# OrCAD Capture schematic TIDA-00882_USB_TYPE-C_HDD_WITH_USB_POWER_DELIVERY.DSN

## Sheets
1 01_BLOCK_DIAGRAM: title: TIDA-00882: USB Type-C HDD; rev: A.0; company: Texas Instruments, CIS/ICP
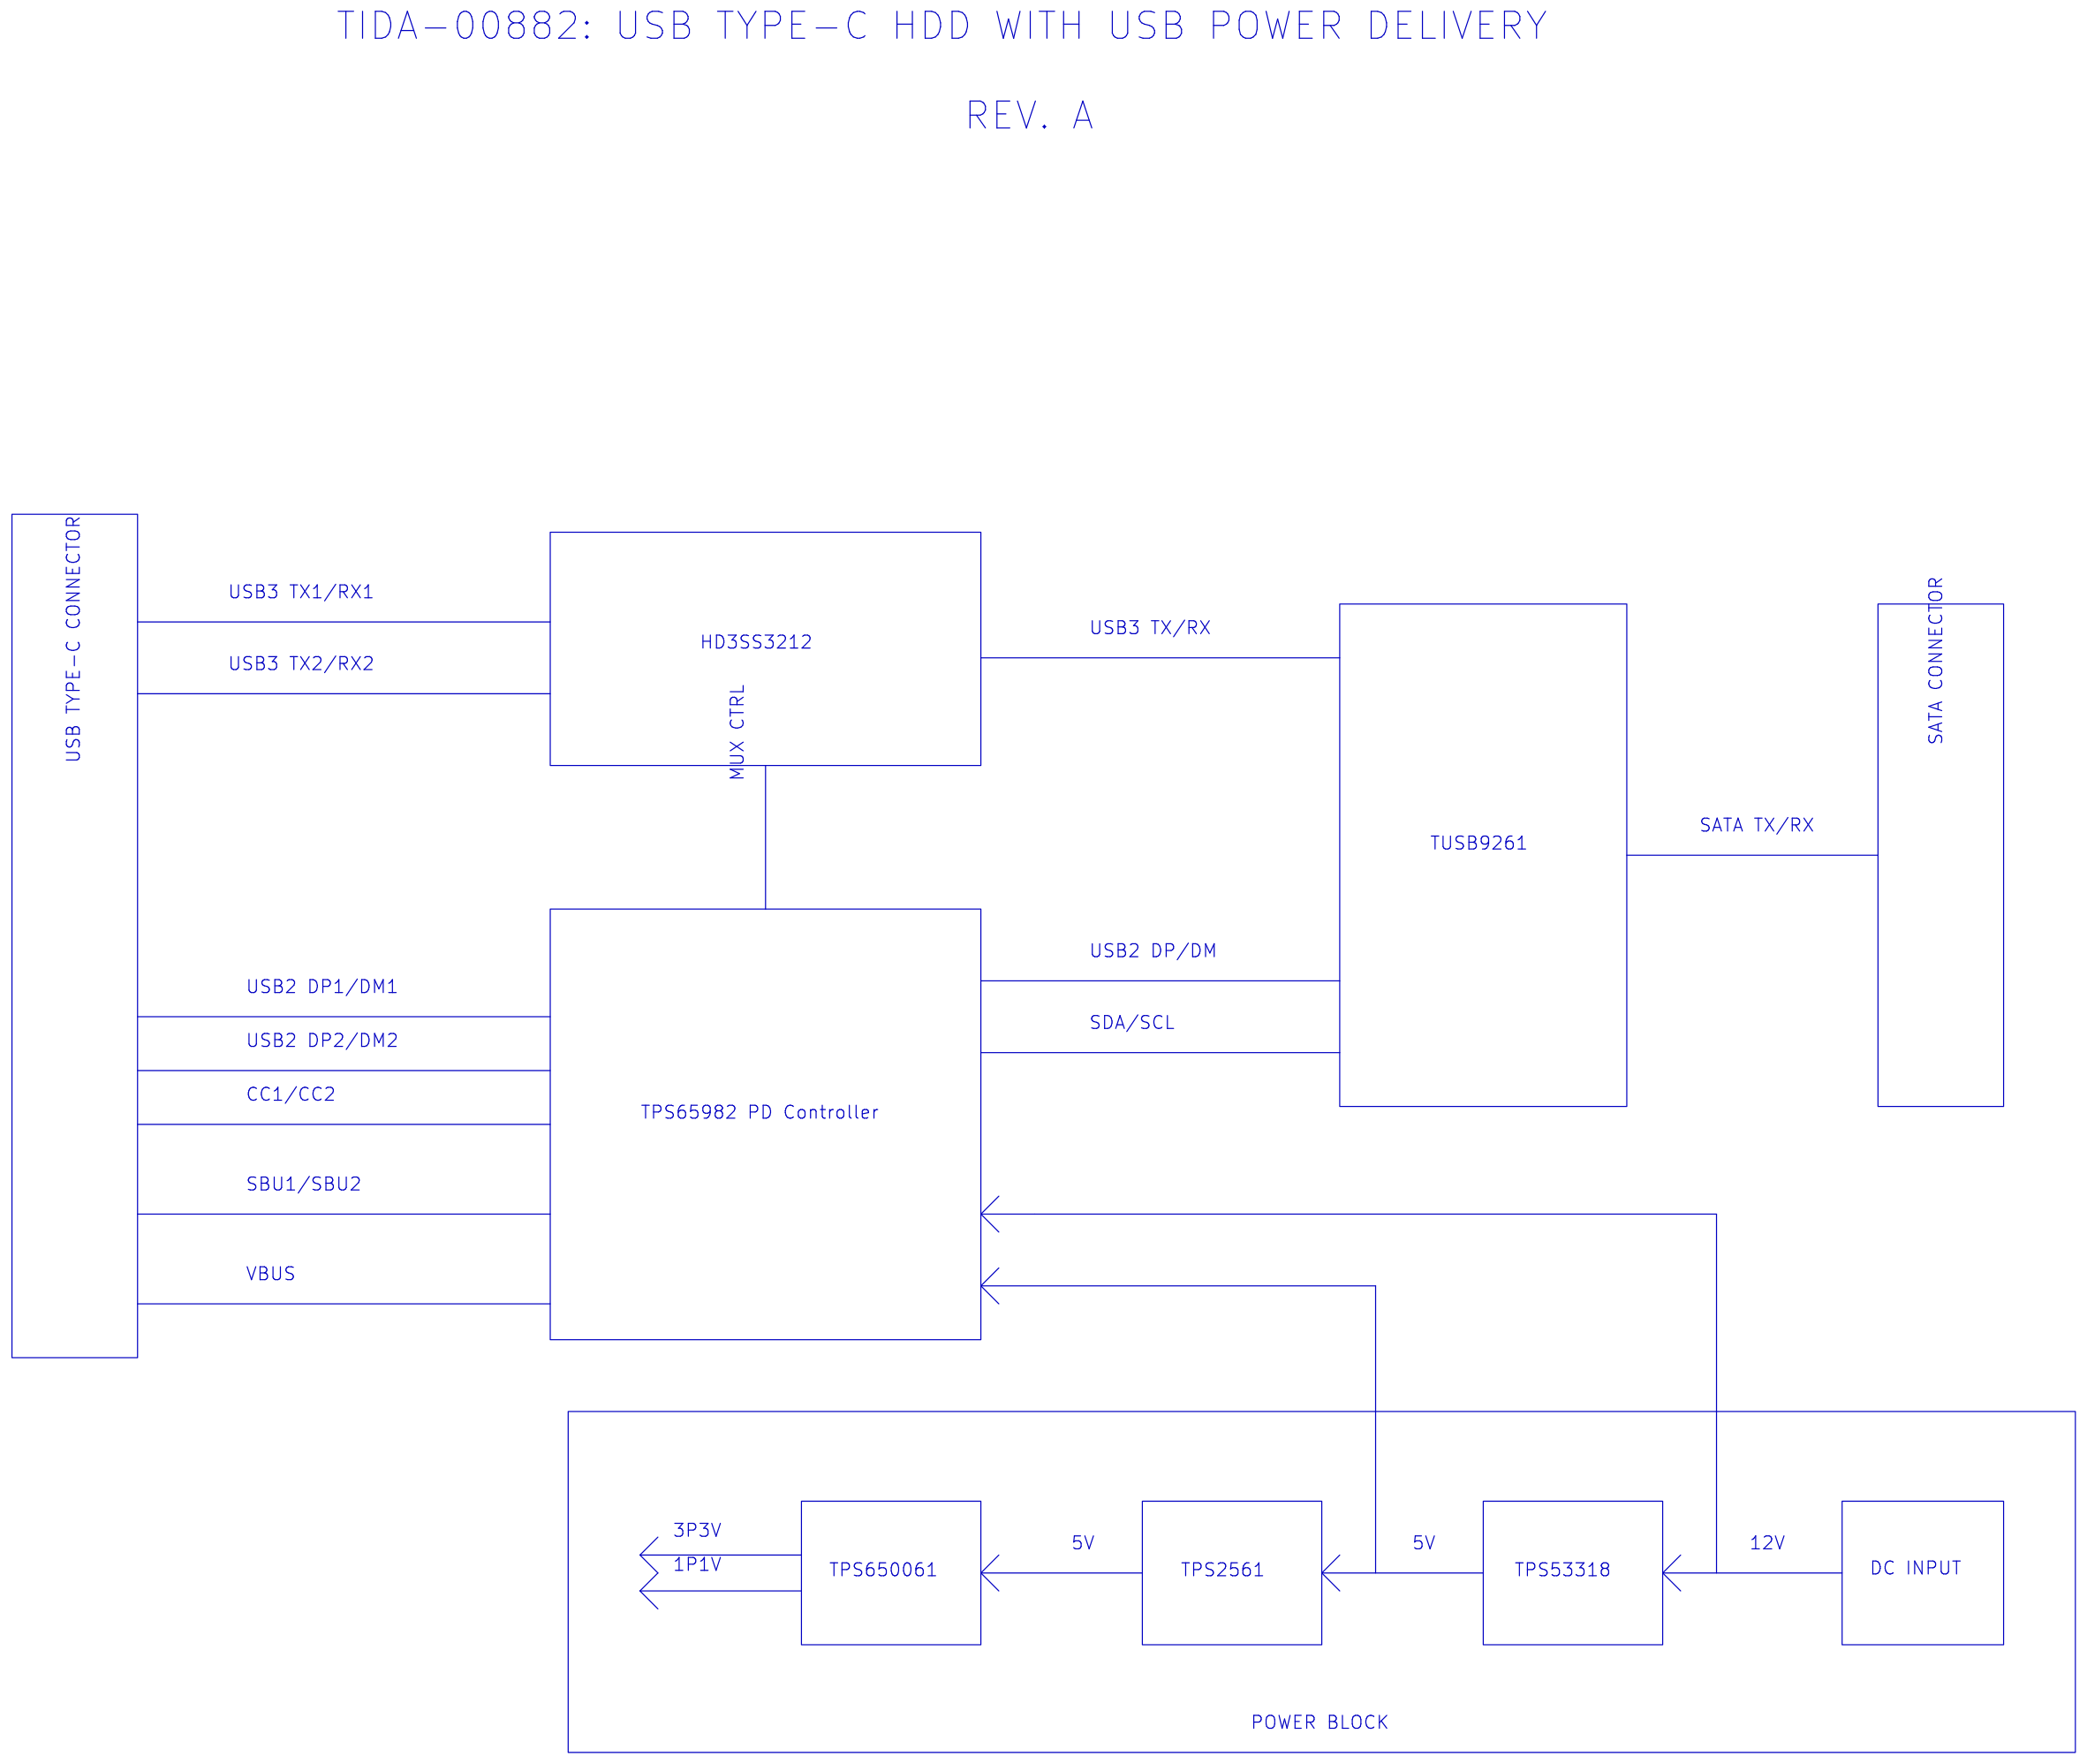
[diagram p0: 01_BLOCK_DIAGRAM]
2 02_HD3SS3212: size C; title: TIDA-00882: USB Type-C HDD: HD3SS3212
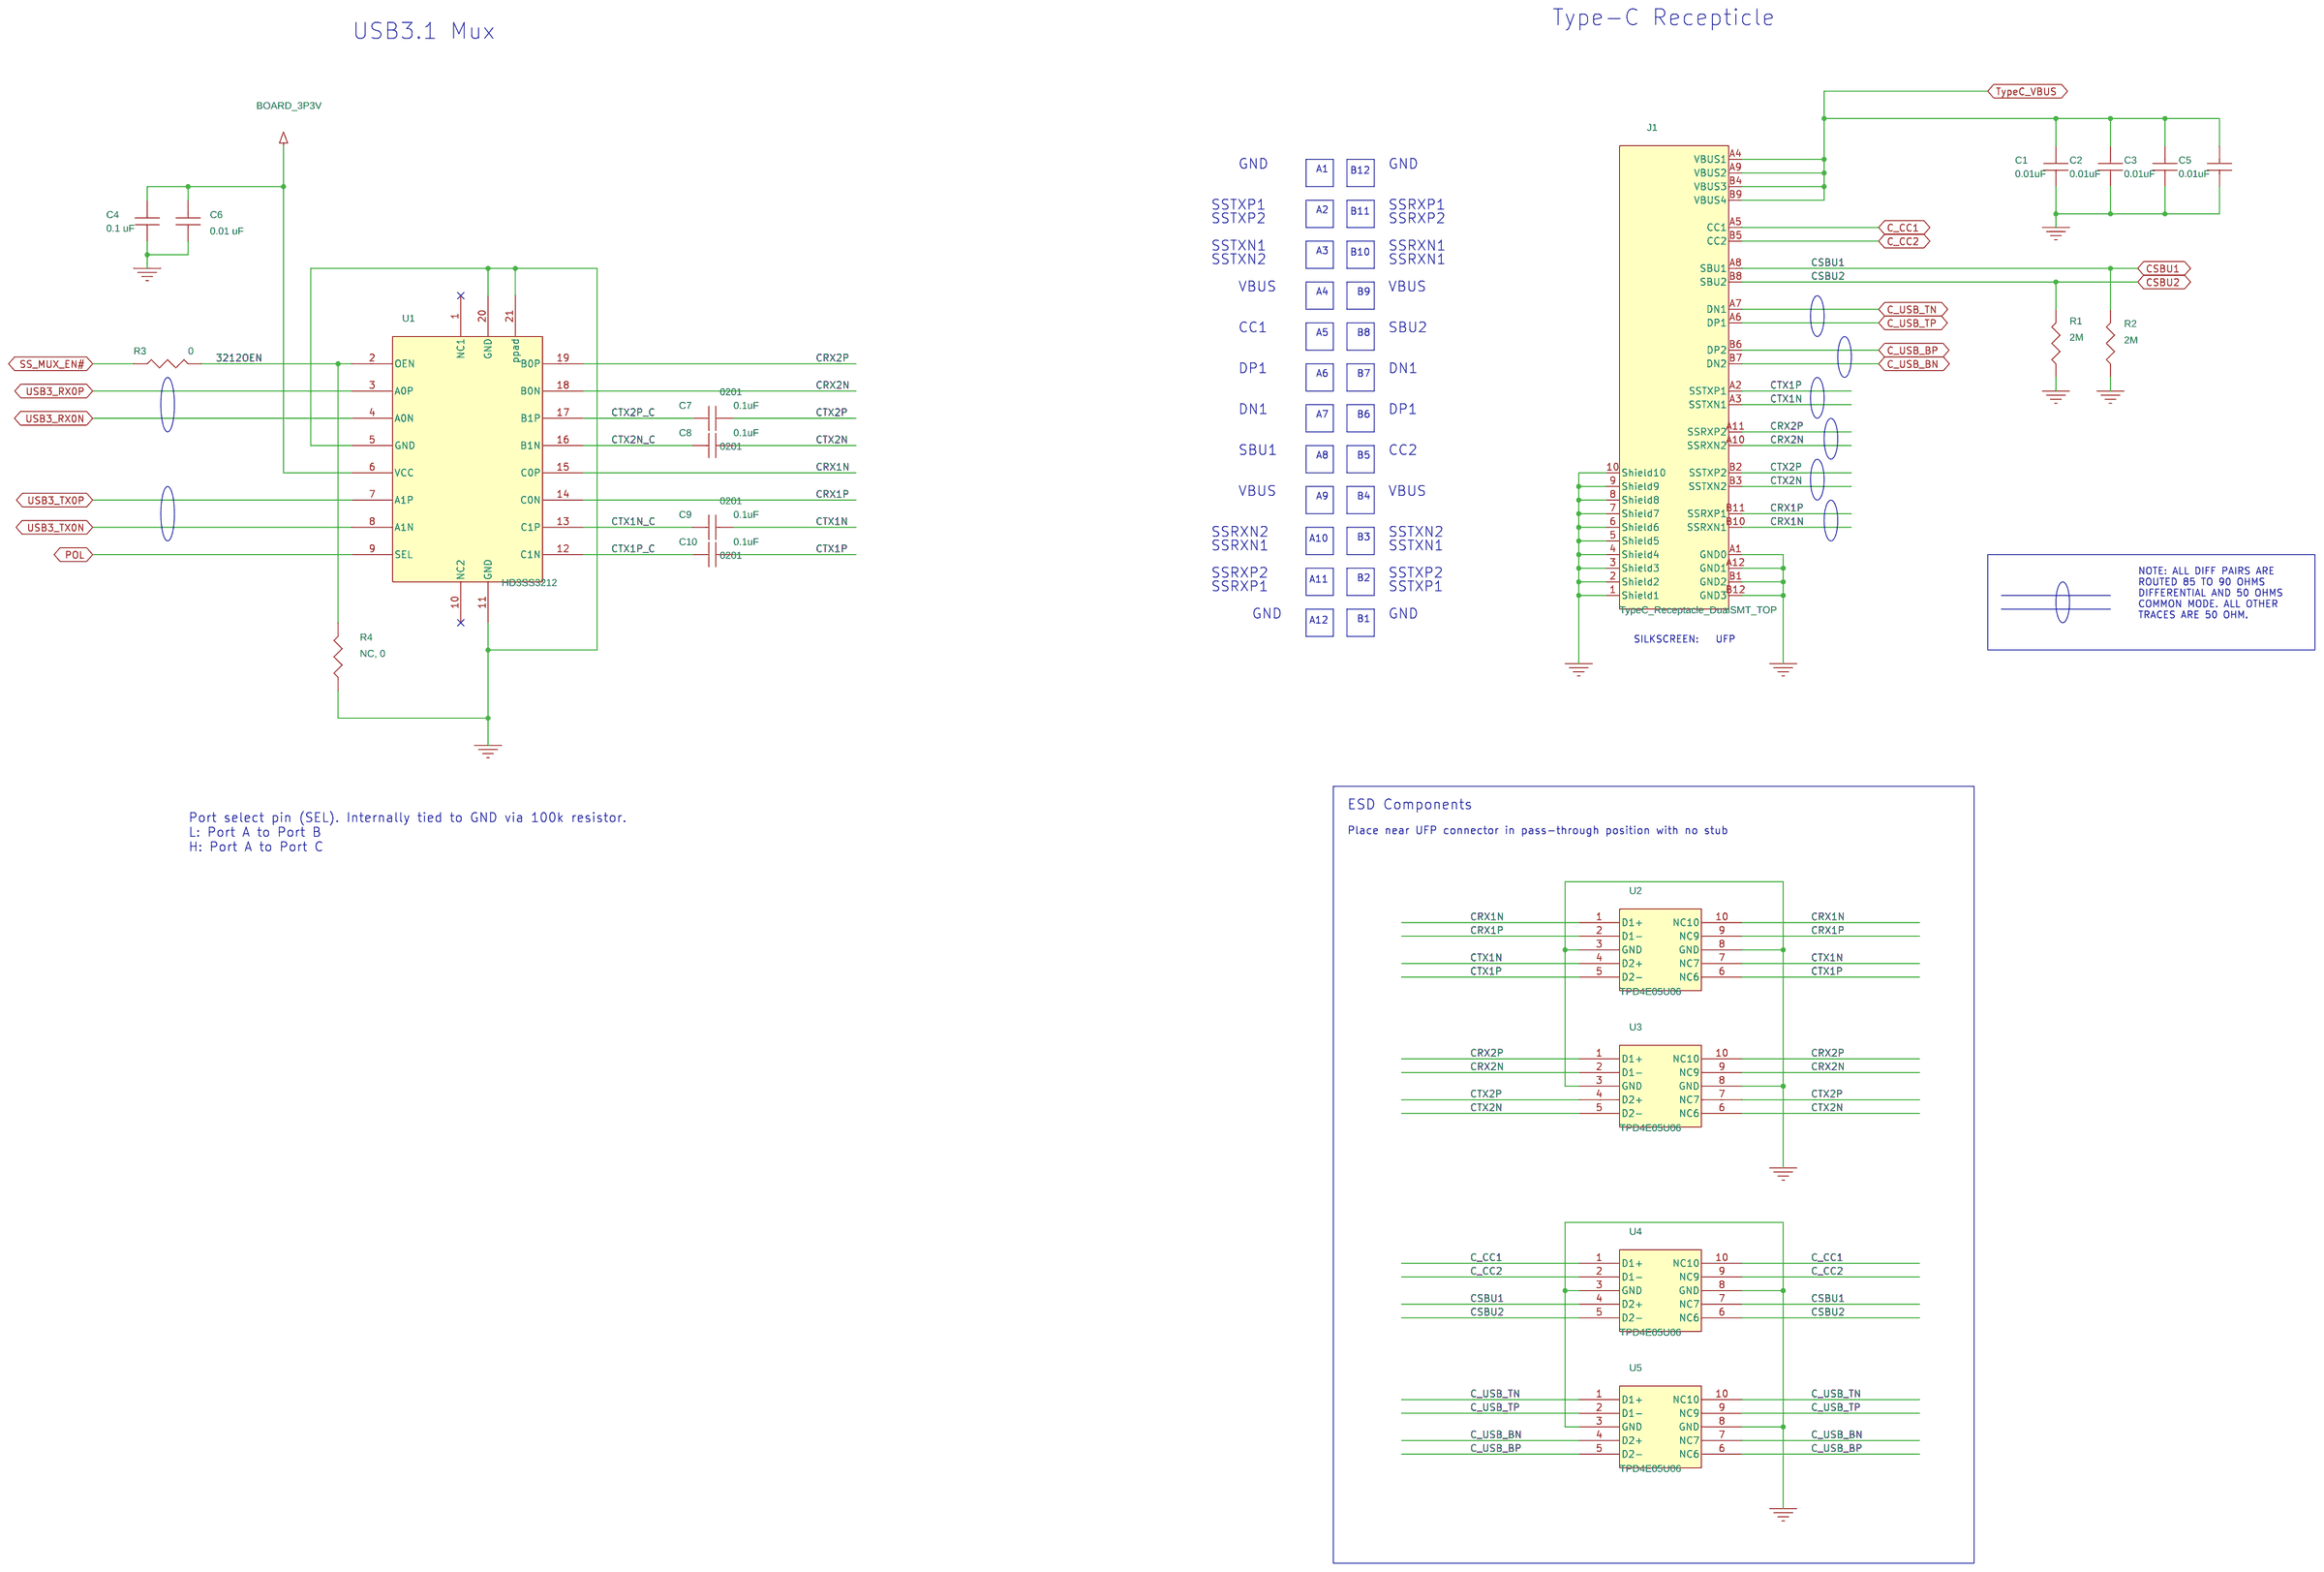
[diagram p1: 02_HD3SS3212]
3 03_TUSB9261: size C; title: TIDA-00882: USB Type-C HDD: TUSB9261
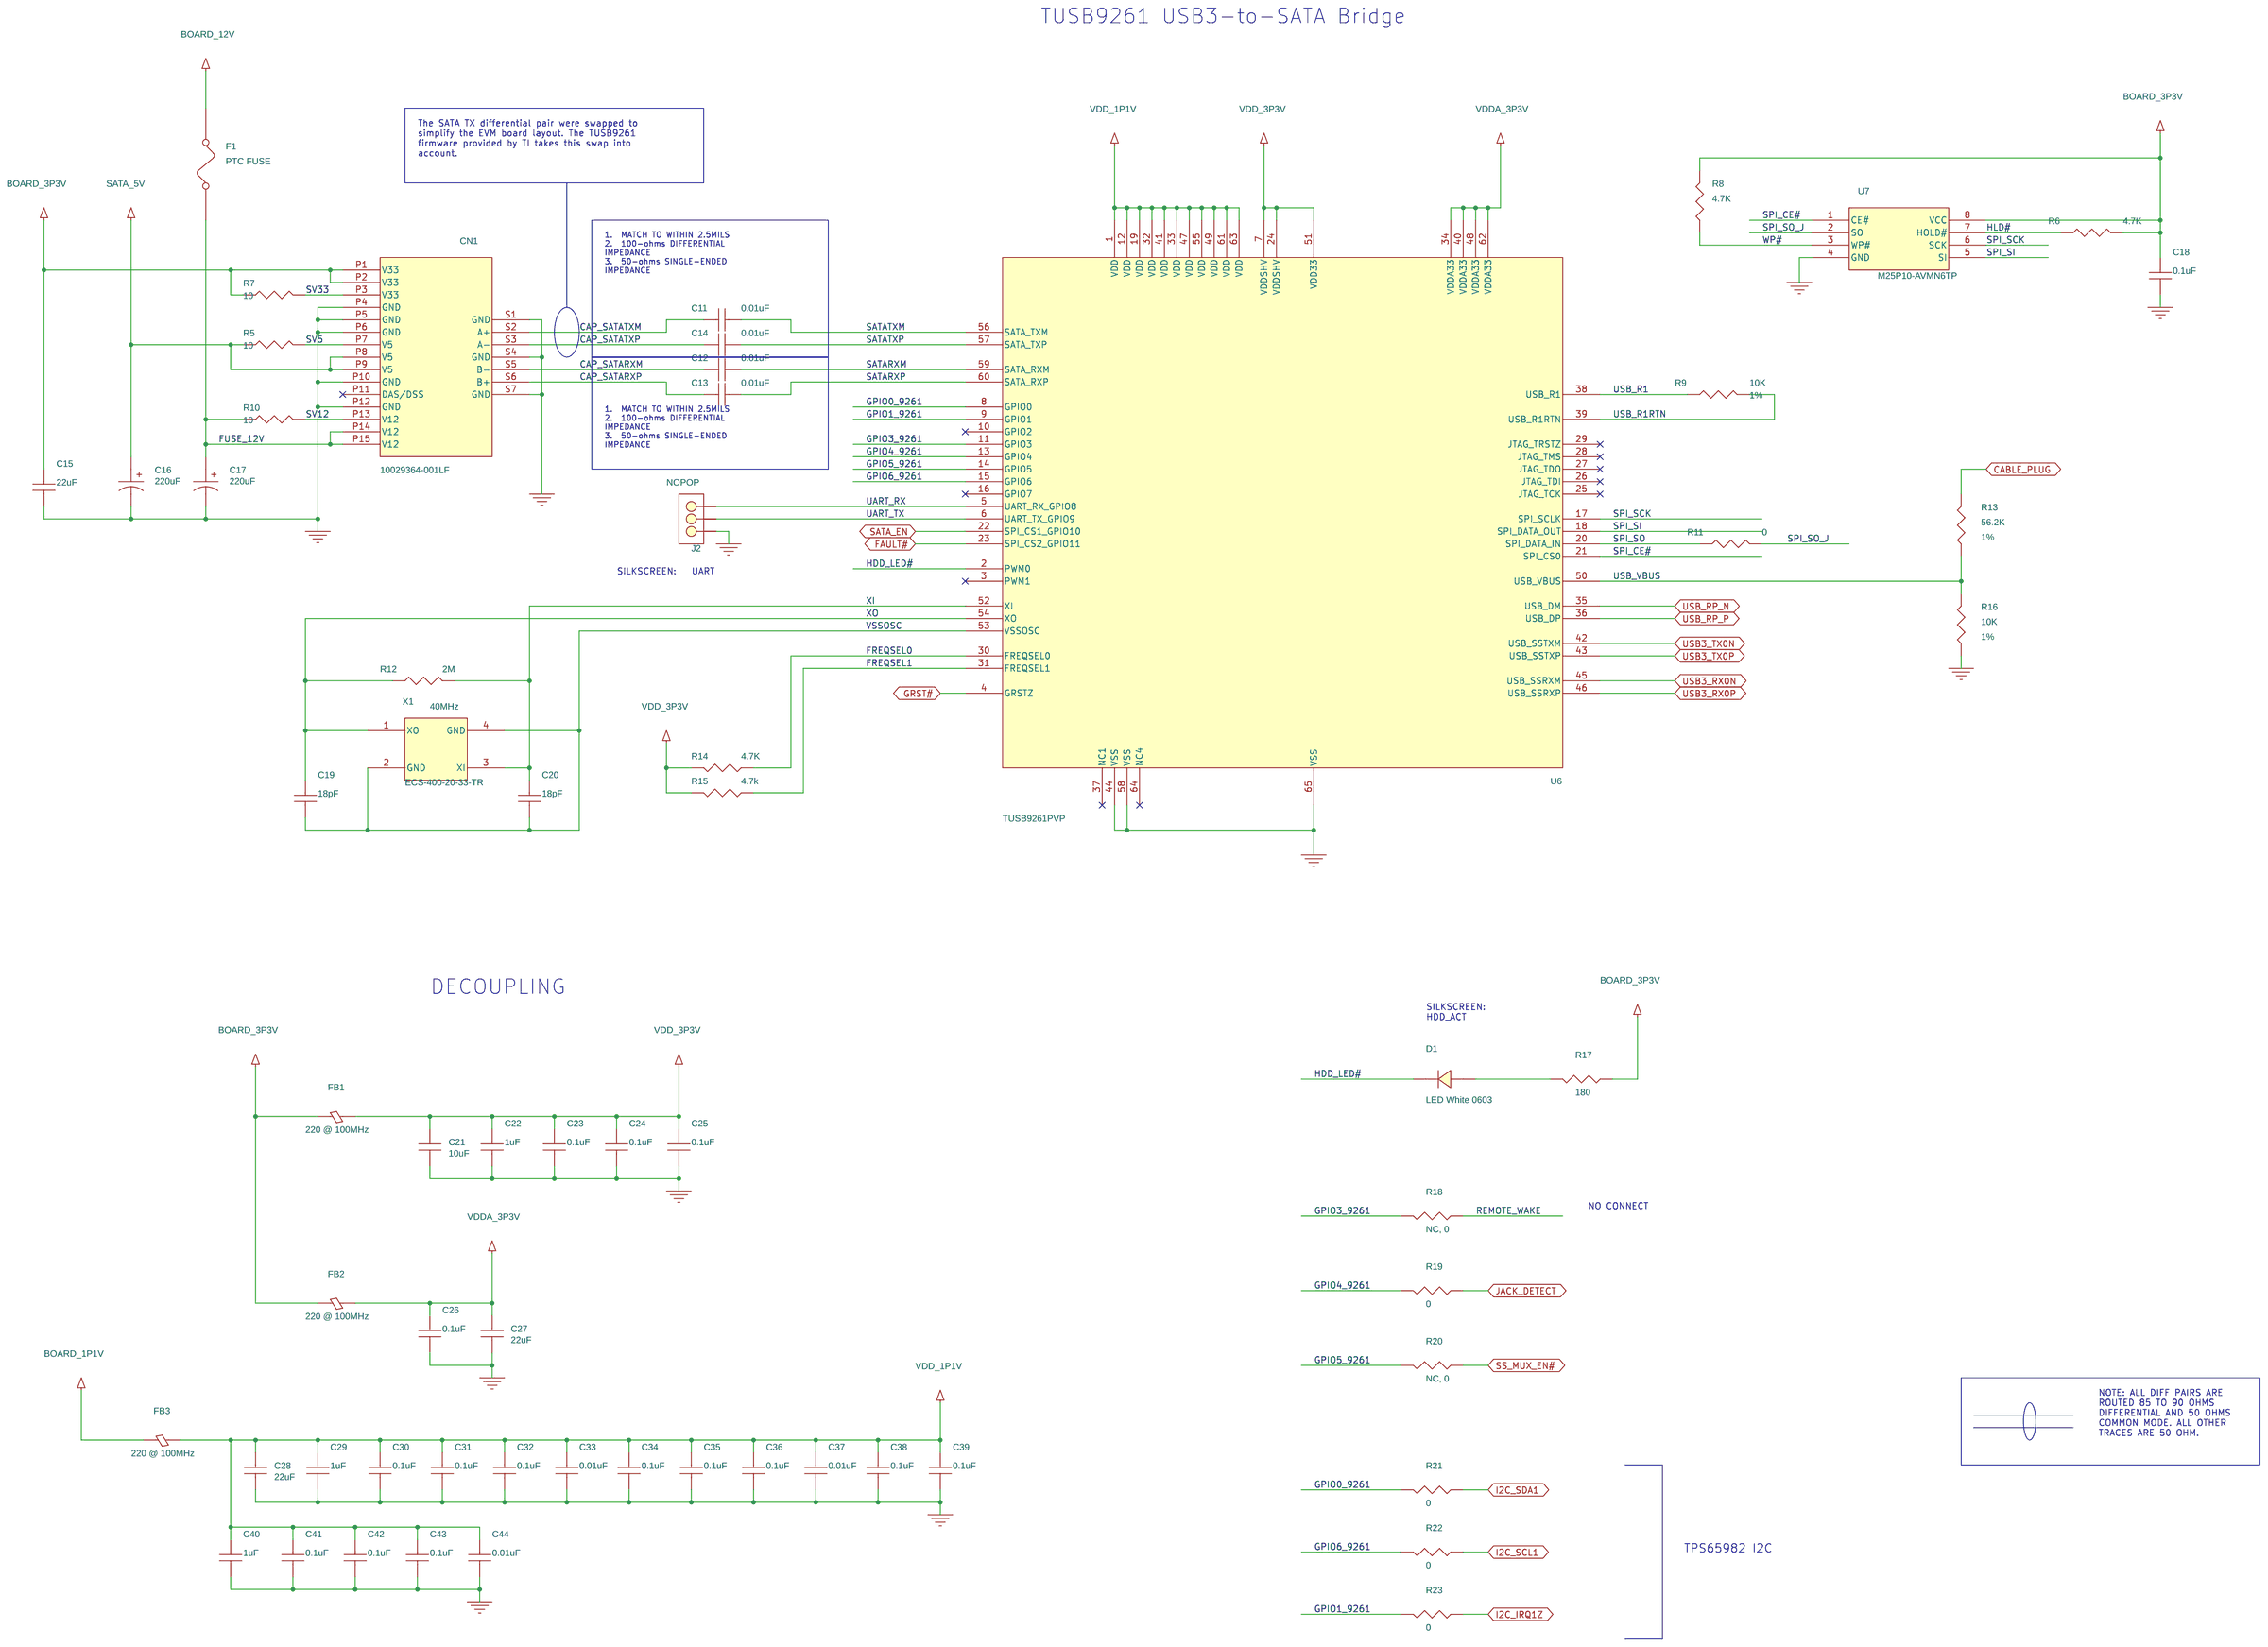
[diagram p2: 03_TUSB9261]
4 04_TPS65982: size C; title: TIDA-00882: USB Type-C HDD: TPS65982
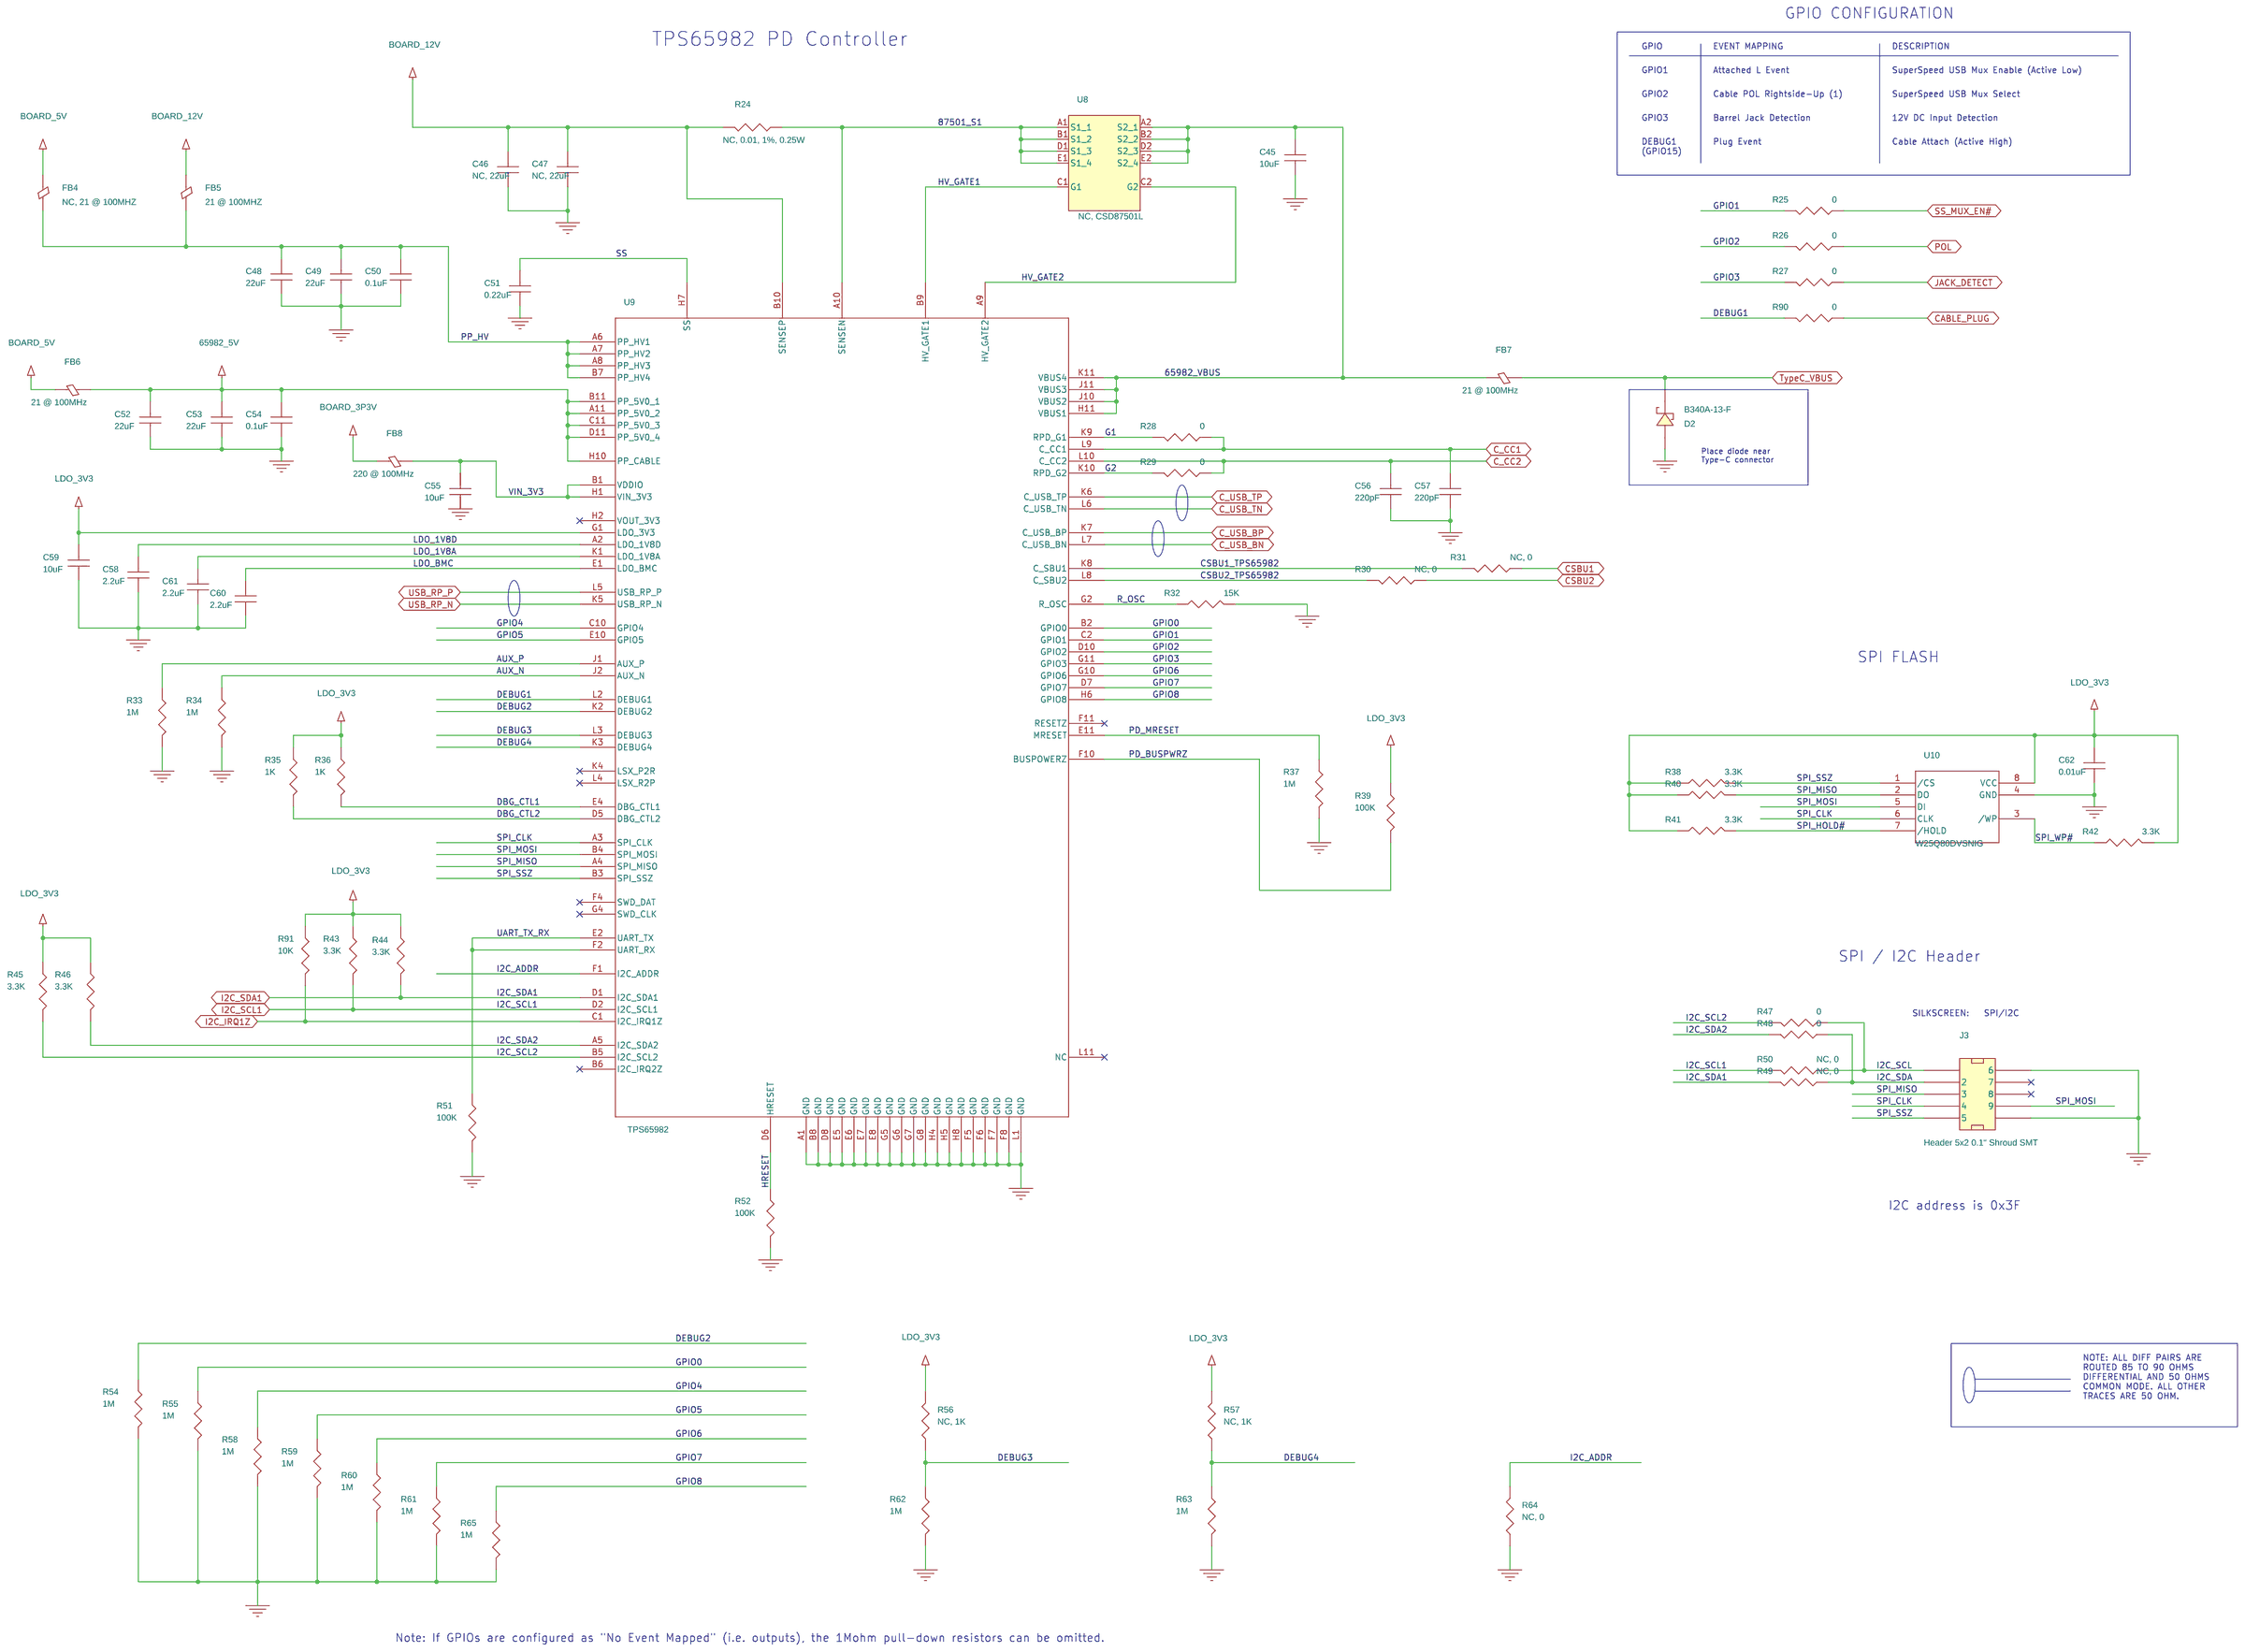
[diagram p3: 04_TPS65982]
5 05_POWER_BLOCK: size C; title: TIDA-00882: USB Type-C HDD: Power Block; rev: A; company: Texas Instruments; note: POWER
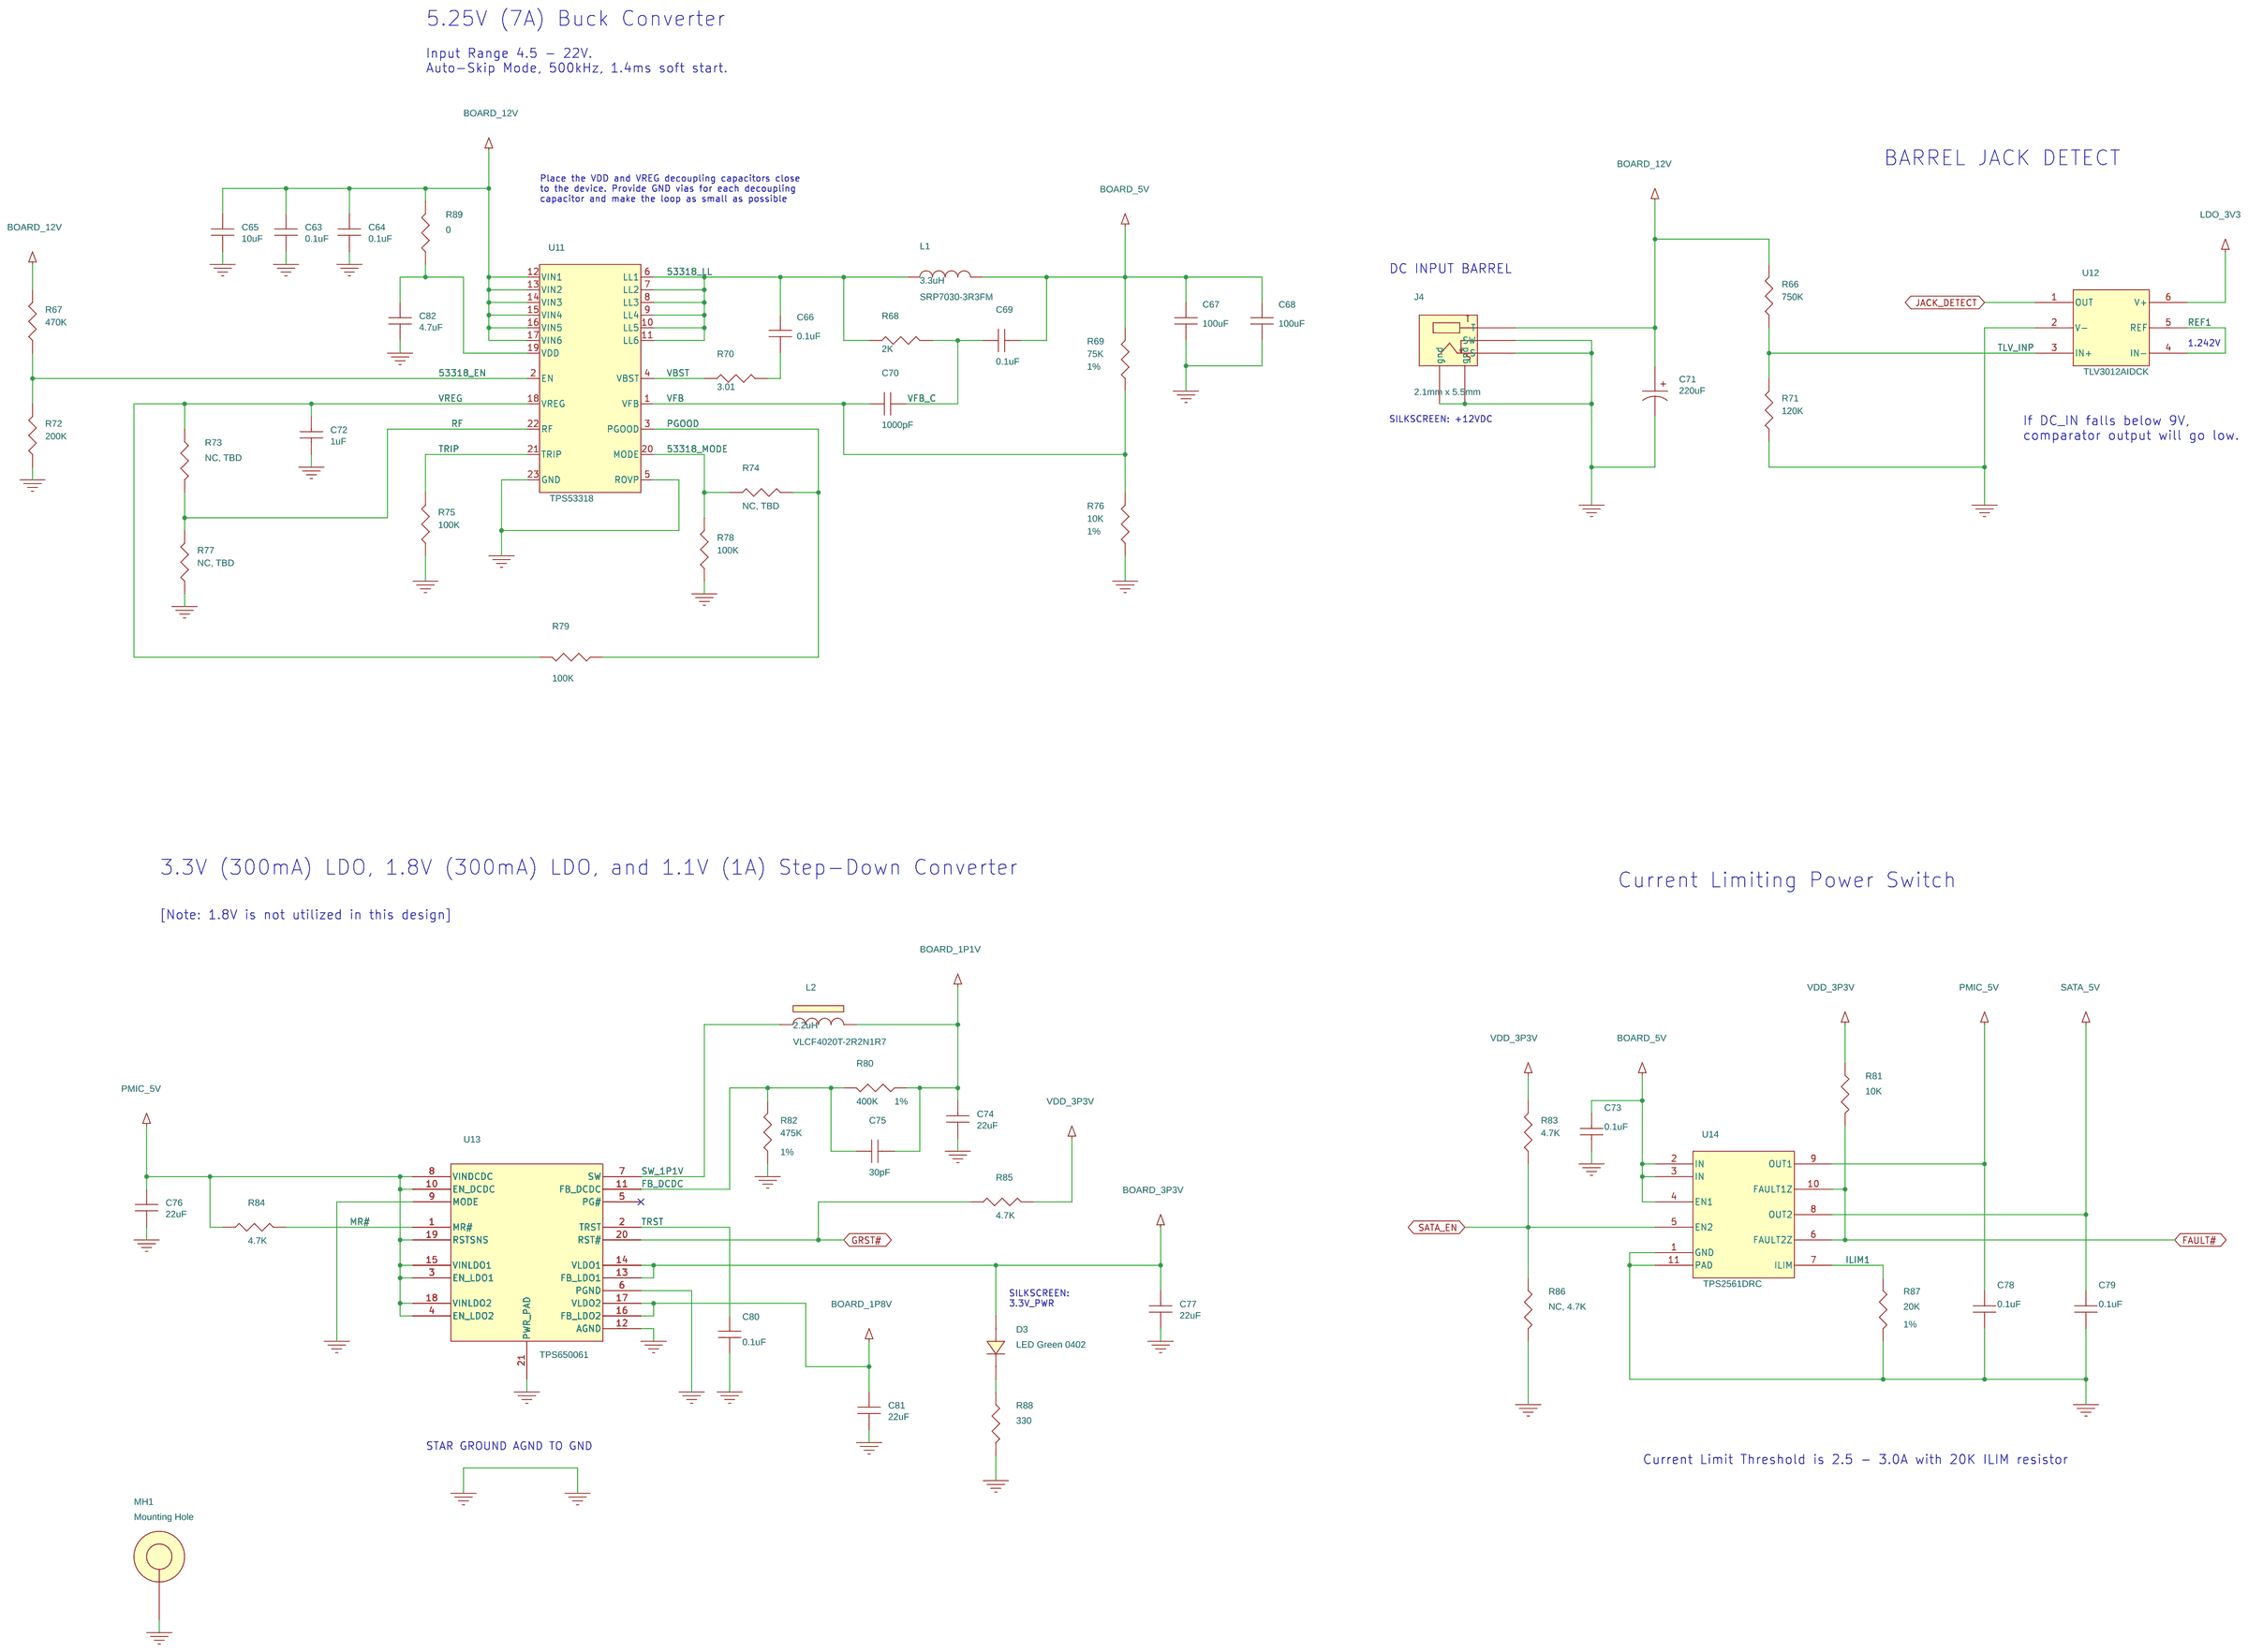
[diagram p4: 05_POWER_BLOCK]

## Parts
sheet 02_HD3SS3212
C1  0.01uF  [0402]
C2  0.01uF  [0402]
C3  0.01uF  [0402]
C4  0.1 uF  [0402]
C5  0.01uF  [0402]
C6  0.01 uF  [0402]
C7  0.1uF  [0201]
C8  0.1uF  [0201]
C9  0.1uF  [0201]
C10  0.1uF  [0201]
J1  TypeC_Receptacle_DualSMT_TOP  [USB_TYPEC_UT1211]
R1  2M  [0201]
R2  2M  [0201]
R3  0  [0402]
R4  NC, 0  [0402]
U1  HD3SS3212  [RKS_R-PVQFN-N20]
U2  TPD4E05U06  [DQA]
U3  TPD4E05U06  [DQA]
U4  TPD4E05U06  [DQA]
U5  TPD4E05U06  [DQA]
sheet 03_TUSB9261
C11  0.01uF  [0402]
C12  0.01uF  [0402]
C13  0.01uF  [0402]
C14  0.01uF  [0402]
C15  22uF  [0603]
C16  220uF  [CAP_RAD_SM_6p3x5p8mm]
C17  220uF  [CAP_RAD_SM_10x8mm]
C18  0.1uF  [0402]
C19  18pF  [0402]
C20  18pF  [0402]
C21  10uF  [0603]
C22  1uF  [0402]
C23  0.1uF  [0402]
C24  0.1uF  [0402]
C25  0.1uF  [0402]
C26  0.1uF  [0402]
C27  22uF  [0603]
C28  22uF  [0603]
C29  1uF  [0402]
C30  0.1uF  [0402]
C31  0.1uF  [0402]
C32  0.1uF  [0402]
C33  0.01uF  [0402]
C34  0.1uF  [0402]
C35  0.1uF  [0402]
C36  0.1uF  [0402]
C37  0.01uF  [0402]
C38  0.1uF  [0402]
C39  0.1uF  [0402]
C40  1uF  [0402]
C41  0.1uF  [0402]
C42  0.1uF  [0402]
C43  0.1uF  [0402]
C44  0.01uF  [0402]
CN1  10029364-001LF  [CON_SMRT_10029364-001LF]
D1  LED White 0603  [0603]
F1  PTC FUSE  [fuse_sm_135x110x43]
FB1  220 @ 100MHz  [0603]
FB2  220 @ 100MHz  [0603]
FB3  220 @ 100MHz  [0603]
J2  NOPOP  [HDR_THVT_1x3_100]
R5  10  [0805]
R6  4.7K  [0402]
R7  10  [0805]
R8  4.7K  [0402]
R9  10K  [0402]
R10  10  [0805]
R11  0  [0402]
R12  2M  [0402]
R13  56.2K  [0402]
R14  4.7K  [0402]
R15  4.7k  [0402]
R16  10K  [0402]
R17  180  [0402]
R18  NC, 0  [0402]
R19  0  [0402]
R20  NC, 0  [0402]
R21  0  [0402]
R22  0  [0402]
R23  0  [0402]
U6  TUSB9261PVP  [pvp_qfp_64]
U7  M25P10-AVMN6TP  [SOIC_8_197x157_50]
X1  40MHz  [ECX-32]
sheet 04_TPS65982
C45  10uF  [0805]
C46  NC, 22uF  [1206]
C47  NC, 22uF  [1206]
C48  22uF  [1206]
C49  22uF  [1206]
C50  0.1uF  [0402]
C51  0.22uF  [0402]
C52  22uF  [0603]
C53  22uF  [0603]
C54  0.1uF  [0402]
C55  10uF  [0603]
C56  220pF  [0402]
C57  220pF  [0402]
C58  2.2uF  [0402]
C59  10uF  [0603]
C60  2.2uF  [0402]
C61  2.2uF  [0402]
C62  0.01uF  [0402]
D2  B340A-13-F  [SMA]
FB4  NC, 21 @ 100MHZ  [0805]
FB5  21 @ 100MHZ  [0805]
FB6  21 @ 100MHz  [0805]
FB7  21 @ 100MHz  [0805]
FB8  220 @ 100MHz  [0603]
J3  Header 5x2 0.1" Shroud SMT  [hdr_smvt_shrd_2x5_100]
R24  NC, 0.01, 1%, 0.25W  [0805]
R25  0  [0402]
R26  0  [0402]
R27  0  [0402]
R28  0  [0201]
R29  0  [0201]
R30  NC, 0  [0201]
R31  NC, 0  [0201]
R32  15K  [0402]
R33  1M  [0201]
R34  1M  [0201]
R35  1K  [0402]
R36  1K  [0402]
R37  1M  [0201]
R38  3.3K  [0402]
R39  100K  [0402]
R40  3.3K  [0402]
R41  3.3K  [0402]
R42  3.3K  [0402]
R43  3.3K  [0402]
R44  3.3K  [0402]
R45  3.3K  [0402]
R46  3.3K  [0402]
R47  0  [0402]
R48  0  [0402]
R49  NC, 0  [0402]
R50  NC, 0  [0402]
R51  100K  [0402]
R52  100K  [0402]
R54  1M  [0201]
R55  1M  [0201]
R56  NC, 1K  [0201]
R57  NC, 1K  [0201]
R58  1M  [0201]
R59  1M  [0201]
R60  1M  [0201]
R61  1M  [0201]
R62  1M  [0201]
R63  1M  [0201]
R64  NC, 0  [0201]
R65  1M  [0201]
R90  0  [0402]
R91  10K  [0402]
U8  NC, CSD87501L  [YJG0010AA]
U9  TPS65982  [ZQZ_BGA_96]
U10  W25Q80DVSNIG  [SOIC_8_197x157_50]
sheet 05_POWER_BLOCK
C63  0.1uF  [0402]
C64  0.1uF  [0402]
C65  10uF  [0805]
C66  0.1uF  [0402]
C67  100uF  [1206]
C68  100uF  [1206]
C69  0.1uF  [0402]
C70  1000pF  [0402]
C71  220uF  [CAP_RAD_SM_10x8mm]
C72  1uF  [0402]
C73  0.1uF  [0402]
C74  22uF  [0603]
C75  30pF  [0402]
C76  22uF  [0603]
C77  22uF  [0603]
C78  0.1uF  [0402]
C79  0.1uF  [0402]
C80  0.1uF  [0402]
C81  22uF  [0603]
C82  4.7uF  [0805]
D3  LED Green 0402  [LED_0402]
J4  2.1mm x 5.5mm  [jack_thrt_PJ-051AH]
L1  3.3uH  [IND_SM_SRP7030F]
L2  2.2uH  [IND_SM_VLCF4020]
MH1  Mounting Hole  [MFG_150_PTH]
R66  750K  [0402]
R67  470K  [0402]
R68  2K  [0402]
R69  75K  [0402]
R70  3.01  [0402]
R71  120K  [0402]
R72  200K  [0402]
R73  NC, TBD  [0402]
R74  NC, TBD  [0402]
R75  100K  [0402]
R76  10K  [0402]
R77  NC, TBD  [0402]
R78  100K  [0402]
R79  100K  [0402]
R80  400K  [0402]
R81  10K  [0402]
R82  475K  [0402]
R83  4.7K  [0402]
R84  4.7K  [0402]
R85  4.7K  [0402]
R86  NC, 4.7K  [0402]
R87  20K  [0402]
R88  330  [0402]
R89  0  [0402]
U11  TPS53318  [DQP_PSON_22]
U12  TLV3012AIDCK  [DCK_PDSO_6]
U13  TPS650061  [RUK_S_PWQFN-N20]
U14  TPS2561DRC  [DRC_S_PVSON_N10]

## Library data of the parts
C1-C6 C51 C54 C55 C58 C60-C62 = cc0402
C7-C10 = CAP_NP: 6.3V Capacitor
J1 = USBTypeC_Receptacle_TOPMount_0: Manufacturer Part Number: UT12113-11601-7H
R1 R2 R25-R52 R54 R55 R58-R63 R65 R90 R91 = R_2: Resistor; Manuf: TBD; Manuf PN: TBD; Tolerance: 5%
R3 R4 = R: Resistor
U1 = HD3SS3212_0: Digi-Key Part Number: 296-42306-1-ND
U2-U5 = TPD4E05U06
C11-C14 C18-C44 C66 C69 C74 C77-C81 = CAP_NP
C15 = CAP_NP: 6.3V
C16 = CAP_POL: 10V; Digi-Key Part Number: 732-6413-1-ND; Manuf: Wurth; Manuf PN: 875105244013
C17 C71 = CAP_POL: 25V; Digi-Key Part Number: 493-13753-1-ND; Manuf: Nichicon; Manuf PN: PCR1E221MCL1GS
CN1 = 0876781001: Manuf: FCI
D1 = DIODE_4: Digi-Key Part Number: VLMW1300-GS08TR-ND; Manufacturer: Vishay; Manufacturer Part Number: VLMW1300-GS08; TI_Silktext: LEDG1
F1 = FUSE: Manuf: Littelfuse; Manuf PN: 1210L110/16WR; Manufacturer: Littelfuse; Manufacturer Part Number: 1210L110/16WR
FB1-FB3 = FERRITE_BEAD: FBEAD 220@100MHz 2A; Device: BEAD1806; Digi-Key Part Number: 490-3992-1-ND; MFC: MuRata; Manuf: MuRata; Manuf PN: BLM18EG221SN1D; Manufacturer: MuRata; Manufacturer Part Number: BLM18EG221SN1D; Part Number: BLM18EG221SN1D; Part#: BLM18EG221SN1D
J2 = HDR3X1_M_.1
R5-R8 R10-R12 R14 R15 R17-R23 R56 R57 R64 R66-R68 R71-R75 R77-R79 R81 R83-R86 R88 = R: Tolerance: 5%
R9 R13 R16 R69 R70 R76 R80 R82 R87 R89 = R: Tolerance: 1%
U6 = TUSB9260PAP_0: Digi-Key Part Number: 296-28827-ND
U7 = Pm25LV512A: Digi-Key Part Number: M25P10-AVMN6TPCT-ND; Manuf: Micron; Manufacturer: Micron
X1 = X_OR_Y_0: Digi-Key Part Number: XC1150CT-ND; Manufacturer: ECS; Manufacturer Part Number: ECS-400-20-33-TR
C45-C50 = cc0402: 25V
C52 C53 = cc0402: 10V
C56 C57 = cc0402: 50V
C59 = cc0402: 6.3V
D2 = DIODE_SCHOTTKY_1: Schottky Diode; Digi-Key Part Number: B340A-FDICT-ND; Manufacturer: Diode
FB4-FB7 = FERRITE_BEAD: FBEAD 21@100MHz; Digi-Key Part Number: 587-1765-1-ND; Manufacturer: Taiyo Yuden; Manufacturer Part Number: FBMJ2125HM210NT
FB8 = FERRITE_BEAD: FBEAD 220@100MHz 2A; Device: BEAD1806; Digi-Key Part Number: 490-3992-1-ND; MFC: MuRata; Manuf: MuRata; Manuf PN: BLM18EG221SN1D; Manufacturer: MuRata; Manufacturer Part Number: BLM18EG221SN1D; Manufacturer's Part Number: BLM18EG221SN1D; Part Number: BLM18EG221SN1D; Part#: BLM18EG221SN1D
J3 = CONN_PCB_5x2-S: Digi-Key Part Number: AE11081-ND; Manufacturer: ASSMANN; Manufacturer Part Number: AWHW-10G-SMD
R24 = RESISTOR: Resistor(3A or above); Manufacturer: Vishay; Manufacturer Part Number: WSL0805R0100FEA18; Tolerance: 1%
U8 = CDS87501L: Digi-Key Part Number: 296-38677-1-ND
U9 = TPS65982: Manufacturer: Texas Instruments
U10 = W25Q80SSI: Digi-Key Part Number: W25Q80DVSNIG-ND
C63 C64 = CAP_NP: 25V; Manufacturer: Chemi-Con; Manufacturer's Part Number: EMVY350ADA4R7MD55G
C65 C82 = CAP_NP: 25V; Manufacturer: MuRata; Manufacturer's Part Number: GRM32ER61E226KE15L
C67 C68 = CAP_NP: 10V; Digi-Key Part Number: 445-11682-1-ND
C70 C73 C76 = CAP_NP: 10V
C72 = CAP_NP: 10V; Manufacturer: MuRata; Manufacturer's Part Number: GRM21BR61C105KA01L
C75 = CAP_NP: 25V
D3 = DIODE_5: Green LED; Digi-Key Part Number: 67-1881-1-ND; Manuf: Lumex; Manuf PN: SML-LX0402SUGC-TR; Manufacturer: Lumex; Manufacturer Part Number: SML-LX0402SUGC-TR; Manufacturer's Part Number: SML-LX0402SUGC-TR
J4 = BNC_0: POWER JACK (15V 5A); Digi-Key Part Number: CP-051AH-ND; Manufacturer: CUI; Manufacturer Part Number: PJ-051AH; PART_NUMBER: 5V_SUPPLY
L1 = INDUCTOR: Digi-Key Part Number: SRP7030-3R3FMCT-ND; Manufacturer: Bourns; Manufacturer Part Number: SRP7030-3R3FM
L2 = INDUCTOR_FERRITE: Digi-Key Part Number: 445-3182-1-ND; Manufacturer: TDK; Manufacturer Part Number: VLCF4020T-2R2N1R7
MH1 = Mounting_Hole
U11 = TPS53318: Digi-Key Part Number: 296-30578-1-ND; Manufacturer: Texas Instruments; Manufacturer's Part Number: TPS53318DQPR
U12 = TLV3012: Digi-Key Part Number: 296-26816-1-ND
U13 = TPS650061_0: Digi-Key Part Number: 296-25358-1-ND
U14 = TPS2560DRC_1: Digi-Key Part Number: 296-25548-1-ND; Manuf: Texas Instruments

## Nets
GND: C1.1 C2.1 C3.1 C4.1 C5.1 C6.1 C15.2 C16.2 C17.2 C18.2 C21.2 C22.2 C23.2 C24.2 C25.2 C26.2 C27.2 C28.2 C29.2 C30.2 C31.2 C32.2 C33.2 C34.2 C35.2 C36.2 C37.2 C38.2 C39.2 C40.2 C41.2 C42.2 C43.2 C44.2 C45.1 C46.1 C47.1 C48.1 C49.1 C50.1 C51.1 C52.1 C53.1 C54.1 C55.1 C56.1 C57.1 C58.1 C59.1 C60.1 C61.1 C62.1 C63.2 C64.2 C65.2 C67.2 C68.2 C71.2 C72.2 C73.2 C74.2 C76.2 C77.2 C78.2 C79.2 C80.2 C81.2 C82.2 CN1.P4(GND) CN1.P5(GND) CN1.P6(GND) CN1.P10(GND) CN1.P12(GND) CN1.S1(GND) CN1.S4(GND) CN1.S7(GND) D2.2(ANODE) J1.1(Shield1) J1.2(Shield2) J1.3(Shield3) J1.4(Shield4) J1.5(Shield5) J1.6(Shield6) J1.7(Shield7) J1.8(Shield8) J1.9(Shield9) J1.10(Shield10) J1.A1(GND0) J1.A12(GND1) J1.B1(GND2) J1.B12(GND3) J2.1 J3.2(6) J3.10 J4.2(S) J4.3(SW) J4.4(gnd) J4.5(gnd) MH1.1(GND) R1.1 R2.1 R4.1 R16.1 R32.2 R33.2 R34.2 R37.2 R51.2 R52.2 R54.2 R55.2 R58.2 R59.2 R60.2 R61.2 R62.2 R63.2 R64.1 R65.2 R71.1 R72.1 R75.1 R76.2 R77.1 R78.1 R82.1 R86.2 R87.2 R88.2 U1.5(GND) U1.11(GND) U1.20(GND) U1.21(ppad) U2.3(GND) U2.8(GND) U3.3(GND) U3.8(GND) U4.3(GND) U4.8(GND) U5.3(GND) U5.8(GND) U6.44(VSS) U6.58(VSS) U6.65(VSS) U7.4(GND) U9.A1(GND) U9.B8(GND) U9.D8(GND) U9.E5(GND) U9.E6(GND) U9.E7(GND) U9.E8(GND) U9.F5(GND) U9.F6(GND) U9.F7(GND) U9.F8(GND) U9.G5(GND) U9.G6(GND) U9.G7(GND) U9.G8(GND) U9.H4(GND) U9.H5(GND) U9.H8(GND) U9.L1(GND) U10.4(GND) U11.5(ROVP) U11.23(GND) U12.2(V-) U13.6(PGND) U13.9(MODE) U13.12(AGND) U13.21(PWR_PAD) U14.1(GND) U14.11(PAD)
SV5: CN1.P7(V5) R5.2
SV12: CN1.P13(V12) R10.2
SV33: CN1.P3(V33) R7.2
VDD_1P1V: C28.1 C29.1 C30.1 C31.1 C32.1 C33.1 C34.1 C35.1 C36.1 C37.1 C38.1 C39.1 C40.1 C41.1 C42.1 C43.1 C44.1 FB3.2 U6.1(VDD) U6.12(VDD) U6.19(VDD) U6.32(VDD) U6.33(VDD) U6.41(VDD) U6.47(VDD) U6.49(VDD) U6.55(VDD) U6.61(VDD) U6.63(VDD)
VDD_3P3V: C21.1 C22.1 C23.1 C24.1 C25.1 FB1.2 R14.2 R15.2 R81.1 R83.2 R85.2 U6.7(VDDSHV) U6.24(VDDSHV) U6.51(VDD33)
VDDA_3P3V: C26.1 C27.1 FB2.2 U6.34(VDDA33) U6.40(VDDA33) U6.48(VDDA33) U6.62(VDDA33)
VIN_3V3: C55.2 FB8.2 U9.B1(VDDIO) U9.H1(VIN_3V3)
VSSOSC: C19.2 C20.2 U6.53(VSSOSC) X1.2(GND) X1.4(GND)
3212OEN: R3.2 R4.2 U1.2(OEN)
53318_EN: R67.1 R72.2 U11.2(EN)
53318_LL: C66.1 L1.1 R68.1 U11.6(LL1) U11.7(LL2) U11.8(LL3) U11.9(LL4) U11.10(LL5) U11.11(LL6)
53318_MODE: R74.1 R78.2 U11.20(MODE)
65982_5V: C52.2 C53.2 C54.2 FB6.2 U9.A11(PP_5V0_2) U9.B11(PP_5V0_1) U9.C11(PP_5V0_3) U9.D11(PP_5V0_4) U9.H10(PP_CABLE)
65982_VBUS: C45.2 FB7.1 U8.A2(S2_1) U8.B2(S2_2) U8.D2(S2_3) U8.E2(S2_4) U9.H11(VBUS1) U9.J10(VBUS2) U9.J11(VBUS3) U9.K11(VBUS4)
87501_S1: R24.1 U8.A1(S1_1) U8.B1(S1_2) U8.D1(S1_3) U8.E1(S1_4) U9.A10(SENSEN)
AUX_N: R34.1 U9.J2(AUX_N)
AUX_P: R33.1 U9.J1(AUX_P)
BOARD_1P1V: C74.1 C75.2 FB3.1 L2.2 R80.1
BOARD_1P8V: C81.1 U13.16(FB_LDO2) U13.17(VLDO2)
BOARD_3P3V: C4.2 C6.2 C15.1 C18.1 C77.1 CN1.P1(V33) CN1.P2(V33) D3.2(A) FB1.1 FB2.1 FB8.1 R6.2 R7.1 R8.2 R17.1 U1.6(VCC) U7.8(VCC) U13.13(FB_LDO1) U13.14(VLDO1)
BOARD_5V: C67.1 C68.1 C69.2 C73.1 FB4.2 FB6.1 L1.2 R69.1 U14.2(IN) U14.3(IN) U14.4(EN1)
BOARD_12V: C46.2 C47.2 C63.1 C64.1 C65.1 C71.1 F1.2 FB5.2 J4.1(T) R24.2 R66.2 R67.2 R89.2 U9.B10(SENSEP) U11.12(VIN1) U11.13(VIN2) U11.14(VIN3) U11.15(VIN4) U11.16(VIN5) U11.17(VIN6)
C_CC1: C57.2 J1.A5(CC1) R28.1 U4.1(D1+) U4.10(NC10) U9.L9(C_CC1)
C_CC2: C56.2 J1.B5(CC2) R29.1 U4.2(D1-) U4.9(NC9) U9.L10(C_CC2)
C_USB_BN: J1.B7(DN2) U5.4(D2+) U5.7(NC7) U9.L7(C_USB_BN)
C_USB_BP: J1.B6(DP2) U5.5(D2-) U5.6(NC6) U9.K7(C_USB_BP)
C_USB_TN: J1.A7(DN1) U5.1(D1+) U5.10(NC10) U9.L6(C_USB_TN)
C_USB_TP: J1.A6(DP1) U5.2(D1-) U5.9(NC9) U9.K6(C_USB_TP)
CABLE_PLUG: R13.2 R90.1
CAP_SATARXM: C12.1 CN1.S5(B-)
CAP_SATARXP: C13.1 CN1.S6(B+)
CAP_SATATXM: C11.1 CN1.S2(A+)
CAP_SATATXP: C14.1 CN1.S3(A-)
CRX1N: J1.B10(SSRXN1) U1.15(C0P) U2.1(D1+) U2.10(NC10)
CRX1P: J1.B11(SSRXP1) U1.14(C0N) U2.2(D1-) U2.9(NC9)
CRX2N: J1.A10(SSRXN2) U1.18(B0N) U3.2(D1-) U3.9(NC9)
CRX2P: J1.A11(SSRXP2) U1.19(B0P) U3.1(D1+) U3.10(NC10)
CSBU1: J1.A8(SBU1) R2.2 R31.1 U4.4(D2+) U4.7(NC7)
CSBU1_TPS65982: R31.2 U9.K8(C_SBU1)
CSBU2: J1.B8(SBU2) R1.2 R30.1 U4.5(D2-) U4.6(NC6)
CSBU2_TPS65982: R30.2 U9.L8(C_SBU2)
CTX1N: C9.2 J1.A3(SSTXN1) U2.4(D2+) U2.7(NC7)
CTX1N_C: C9.1 U1.13(C1P)
CTX1P: C10.2 J1.A2(SSTXP1) U2.5(D2-) U2.6(NC6)
CTX1P_C: C10.1 U1.12(C1N)
CTX2N: C8.2 J1.B3(SSTXN2) U3.5(D2-) U3.6(NC6)
CTX2N_C: C8.1 U1.16(B1N)
CTX2P: C7.2 J1.B2(SSTXP2) U3.4(D2+) U3.7(NC7)
CTX2P_C: C7.1 U1.17(B1P)
DBG_CTL1: R36.2 U9.E4(DBG_CTL1)
DBG_CTL2: R35.2 U9.D5(DBG_CTL2)
DEBUG1: R90.2 U9.L2(DEBUG1)
DEBUG2: R54.1 U9.K2(DEBUG2)
DEBUG3: R56.1 R62.1 U9.L3(DEBUG3)
DEBUG4: R57.1 R63.1 U9.K3(DEBUG4)
FAULT#: R81.2 U6.23(SPI_CS2_GPIO11) U14.6(FAULT2Z) U14.10(FAULT1Z)
FB_DCDC: C75.1 R80.2 R82.2 U13.11(FB_DCDC)
FREQSEL0: R14.1 U6.30(FREQSEL0)
FREQSEL1: R15.1 U6.31(FREQSEL1)
FUSE_12V: C17.1 CN1.P14(V12) CN1.P15(V12) F1.1 R10.1
G1: R28.2 U9.K9(RPD_G1)
G2: R29.2 U9.K10(RPD_G2)
GPIO0: R55.1 U9.B2(GPIO0)
GPIO0_9261: R21.2 U6.8(GPIO0)
GPIO1: R25.2 U9.C2(GPIO1)
GPIO1_9261: R23.2 U6.9(GPIO1)
GPIO2: R26.2 U9.D10(GPIO2)
GPIO3: R27.2 U9.G11(GPIO3)
GPIO3_9261: R18.2 U6.11(GPIO3)
GPIO4: R58.1 U9.C10(GPIO4)
GPIO4_9261: R19.2 U6.13(GPIO4)
GPIO5: R59.1 U9.E10(GPIO5)
GPIO5_9261: R20.2 U6.14(GPIO5)
GPIO6: R60.1 U9.G10(GPIO6)
GPIO6_9261: R22.2 U6.15(GPIO6)
GPIO7: R61.1 U9.D7(GPIO7)
GPIO8: R65.1 U9.H6(GPIO8)
GRST#: R85.1 U6.4(GRSTZ) U13.20(RST#)
HDD_LED#: D1.1(K) U6.2(PWM0)
HLD#: R6.1 U7.7(HOLD#)
HRESET: R52.1 U9.D6(HRESET)
HV_GATE1: U8.C1(G1) U9.B9(HV_GATE1)
HV_GATE2: U8.C2(G2) U9.A9(HV_GATE2)
I2C_ADDR: R64.2 U9.F1(I2C_ADDR)
I2C_IRQ1Z: R23.1 R91.2 U9.C1(I2C_IRQ1Z)
I2C_SCL: J3.1 R47.1 R50.1
I2C_SCL1: R22.1 R43.2 R50.2 U9.D2(I2C_SCL1)
I2C_SCL2: R45.2 R47.2 U9.B5(I2C_SCL2)
I2C_SDA: J3.3(2) R48.1 R49.1
I2C_SDA1: R21.1 R44.2 R49.2 U9.D1(I2C_SDA1)
I2C_SDA2: R46.2 R48.2 U9.A5(I2C_SDA2)
ILIM1: R87.1 U14.7(ILIM)
JACK_DETECT: R19.1 R27.1 U12.1(OUT)
LDO_1V8A: C61.2 U9.K1(LDO_1V8A)
LDO_1V8D: C58.2 U9.A2(LDO_1V8D)
LDO_3V3: C59.2 C62.2 R35.1 R36.1 R38.1 R39.1 R40.1 R41.1 R42.2 R43.1 R44.1 R45.1 R46.1 R56.2 R57.2 R91.1 U9.G1(LDO_3V3) U10.8(VCC) U12.6(V+)
LDO_BMC: C60.2 U9.E1(LDO_BMC)
MR#: R84.2 U13.1(MR#)
PD_BUSPWRZ: R39.2 U9.F10(BUSPOWERZ)
PD_MRESET: R37.1 U9.E11(MRESET)
PGOOD: R74.2 R79.1 U11.3(PGOOD)
PMIC_5V: C76.1 C78.1 R84.1 U13.3(EN_LDO1) U13.4(EN_LDO2) U13.8(VINDCDC) U13.10(EN_DCDC) U13.15(VINLDO1) U13.18(VINLDO2) U13.19(RSTSNS) U14.9(OUT1)
POL: R26.1 U1.9(SEL)
PP_HV: C48.2 C49.2 C50.2 FB4.1 FB5.1 U9.A6(PP_HV1) U9.A7(PP_HV2) U9.A8(PP_HV3) U9.B7(PP_HV4)
R_OSC: R32.1 U9.G2(R_OSC)
REF1: U12.4(IN-) U12.5(REF)
REMOTE_WAKE: R18.1
RF: R73.2 R77.2 U11.22(RF)
SATA_5V: C16.1 C79.1 CN1.P8(V5) CN1.P9(V5) R5.1 U14.8(OUT2)
SATA_EN: R83.1 R86.1 U6.22(SPI_CS1_GPIO10) U14.5(EN2)
SATARXM: C12.2 U6.59(SATA_RXM)
SATARXP: C13.2 U6.60(SATA_RXP)
SATATXM: C11.2 U6.56(SATA_TXM)
SATATXP: C14.2 U6.57(SATA_TXP)
SPI_CE#: U6.21(SPI_CS0) U7.1(CE#)
SPI_CLK: J3.7(4) U9.A3(SPI_CLK) U10.6(CLK)
SPI_HOLD#: R41.2 U10.7(/HOLD)
SPI_MISO: J3.5(3) R40.2 U9.A4(SPI_MISO) U10.2(DO)
SPI_MOSI: J3.8(9) U9.B4(SPI_MOSI) U10.5(DI)
SPI_SCK: U6.17(SPI_SCLK) U7.6(SCK)
SPI_SI: U6.18(SPI_DATA_OUT) U7.5(SI)
SPI_SO: R11.1 U6.20(SPI_DATA_IN)
SPI_SO_J: R11.2 U7.2(SO)
SPI_SSZ: J3.9(5) R38.2 U9.B3(SPI_SSZ) U10.1(/CS)
SPI_WP#: R42.1 U10.3(/WP)
SS: C51.2 U9.H7(SS)
SS_MUX_EN#: R3.1 R20.1 R25.1
SW_1P1V: L2.1 U13.7(SW)
TLV_INP: R66.1 R71.2 U12.3(IN+)
TRIP: R75.2 U11.21(TRIP)
TRST: C80.1 U13.2(TRST)
TypeC_VBUS: C1.2 C2.2 C3.2 C5.2 D2.1(CATHODE) FB7.2 J1.A4(VBUS1) J1.A9(VBUS2) J1.B4(VBUS3) J1.B9(VBUS4)
UART_RX: J2.3 U6.5(UART_RX_GPIO8)
UART_TX: J2.2 U6.6(UART_TX_GPIO9)
UART_TX_RX: R51.1 U9.E2(UART_TX) U9.F2(UART_RX)
USB3_RX0N: U1.4(A0N) U6.45(USB_SSRXM)
USB3_RX0P: U1.3(A0P) U6.46(USB_SSRXP)
USB3_TX0N: U1.8(A1N) U6.42(USB_SSTXM)
USB3_TX0P: U1.7(A1P) U6.43(USB_SSTXP)
USB_R1: R9.1 U6.38(USB_R1)
USB_R1RTN: R9.2 U6.39(USB_R1RTN)
USB_RP_N: U6.35(USB_DM) U9.K5(USB_RP_N)
USB_RP_P: U6.36(USB_DP) U9.L5(USB_RP_P)
USB_VBUS: R13.1 R16.2 U6.50(USB_VBUS)
VBST: R70.1 U11.4(VBST)
VFB: C70.1 R69.2 R76.1 U11.1(VFB)
VFB_C: C69.1 C70.2 R68.2
VREG: C72.1 R73.1 R79.2 U11.18(VREG)
WP#: R8.1 U7.3(WP#)
XI: C20.1 R12.2 U6.52(XI) X1.3(XI)
XO: C19.1 R12.1 U6.54(XO) X1.1(XO)
N17726709: D1.2(A) R17.2
N17832078: C82.1 R89.1 U11.19(VDD)
N17839350: C66.2 R70.2
N17883338: D3.1(K) R88.1

Not connected (* = marked no-connect by the designer): CN1 P11(DAS/DSS)*; J3 4(7)* 6(8)*; U1 1(NC1)* 10(NC2)*; U6 3(PWM1)* 10(GPIO2)* 16(GPIO7)* 25(JTAG_TCK)* 26(JTAG_TDI)* 27(JTAG_TDO)* 28(JTAG_TMS)* 29(JTAG_TRSTZ)* 37(NC1)* 64(NC4)*; U9 B6(I2C_IRQ2Z)* F4(SWD_DAT)* F11(RESETZ)* G4(SWD_CLK)* H2(VOUT_3V3)* K4(LSX_P2R)* L4(LSX_R2P)* L11(NC)*; U13 5(PG#)*

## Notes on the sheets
sheet 1
- TIDA-00882: USB TYPE-C HDD WITH USB POWER DELIVERY
- REV. A
- USB3 TX1/RX1
- USB3 TX/RX
- HD3SS3212
- USB3 TX2/RX2
- SATA CONNECTOR
- USB TYPE-C CONNECTOR
- MUX CTRL
- SATA TX/RX
- TUSB9261
- USB2 DP/DM
- USB2 DP1/DM1
- SDA/SCL
- USB2 DP2/DM2
- CC1/CC2
- TPS65982 PD Controller
- SBU1/SBU2
- VBUS
- 3P3V
- 5V
- 5V
- 12V
- 1P1V
- DC INPUT
- TPS650061
- TPS2561
- TPS53318
- POWER BLOCK
sheet 2
- Type-C Recepticle
- USB3.1 Mux
- GND
- GND
- A1
- B12
- SSTXP1
- A2
- B11
- SSRXP1
- SSTXP2
- SSRXP2
- SSTXN1
- SSRXN1
- SSTXN2
- A3
- B10
- SSRXN1
- VBUS
- A4
- B9
- VBUS
- CC1
- SBU2
- A5
- B8
- DP1
- A6
- B7
- DN1
- DN1
- A7
- B6
- DP1
- SBU1
- CC2
- A8
- B5
- VBUS
- A9
- B4
- VBUS
- SSRXN2
- SSTXN2
- SSRXN1
- A10
- B3
- SSTXN1
- SSRXP2
- A11
- B2
- SSTXP2
- NOTE: ALL DIFF PAIRS ARE
  ROUTED 85 TO 90 OHMS
  DIFFERENTIAL AND 50 OHMS
  COMMON MODE. ALL OTHER
  TRACES ARE 50 OHM.
- SSRXP1
- SSTXP1
- GND
- GND
- A12
- B1
- SILKSCREEN:
- UFP
- ESD Components
- Port select pin (SEL). Internally tied to GND via 100k resistor.
  L: Port A to Port B
  H: Port A to Port C
- Place near UFP connector in pass-through position with no stub
sheet 3
- TUSB9261 USB3-to-SATA Bridge
- The SATA TX differential pair were swapped to
  simplify the EVM board layout. The TUSB9261
  firmware provided by TI takes this swap into
  account.
- 1.  MATCH TO WITHIN 2.5MILS
  2.  100-ohms DIFFERENTIAL
  IMPEDANCE
  3.  50-ohms SINGLE-ENDED
  IMPEDANCE
- 1.  MATCH TO WITHIN 2.5MILS
  2.  100-ohms DIFFERENTIAL
  IMPEDANCE
  3.  50-ohms SINGLE-ENDED
  IMPEDANCE
- SILKSCREEN:
- UART
- DECOUPLING
- SILKSCREEN:
  HDD_ACT
- NO CONNECT
- NOTE: ALL DIFF PAIRS ARE
  ROUTED 85 TO 90 OHMS
  DIFFERENTIAL AND 50 OHMS
  COMMON MODE. ALL OTHER
  TRACES ARE 50 OHM.
- TPS65982 I2C
sheet 4
- GPIO CONFIGURATION
- TPS65982 PD Controller
- GPIO
- EVENT MAPPING
- DESCRIPTION
- GPIO1
- Attached L Event
- SuperSpeed USB Mux Enable (Active Low)
- GPIO2
- Cable POL Rightside-Up (1)
- SuperSpeed USB Mux Select
- GPIO3
- Barrel Jack Detection
- 12V DC Input Detection
- DEBUG1
  (GPIO15)
- Plug Event
- Cable Attach (Active High)
- Place diode near
  Type-C connector
- SPI FLASH
- SPI / I2C Header
- SILKSCREEN:
- SPI/I2C
- I2C address is 0x3F
- NOTE: ALL DIFF PAIRS ARE
  ROUTED 85 TO 90 OHMS
  DIFFERENTIAL AND 50 OHMS
  COMMON MODE. ALL OTHER
  TRACES ARE 50 OHM.
- Note: If GPIOs are configured as "No Event Mapped" (i.e. outputs), the 1Mohm pull-down resistors can be omitted.
sheet 5
- 5.25V (7A) Buck Converter
- Input Range 4.5 - 22V.
  Auto-Skip Mode, 500kHz, 1.4ms soft start.
- BARREL JACK DETECT
- Place the VDD and VREG decoupling capacitors close
  to the device. Provide GND vias for each decoupling
  capacitor and make the loop as small as possible
- DC INPUT BARREL
- 1.242V
- SILKSCREEN: +12VDC
- If DC_IN falls below 9V,
  comparator output will go low.
- 3.3V (300mA) LDO, 1.8V (300mA) LDO, and 1.1V (1A) Step-Down Converter
- Current Limiting Power Switch
- [Note: 1.8V is not utilized in this design]
- SILKSCREEN:
  3.3V_PWR
- STAR GROUND AGND TO GND
- Current Limit Threshold is 2.5 - 3.0A with 20K ILIM resistor
